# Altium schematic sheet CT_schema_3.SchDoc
size 283 x 147 mm
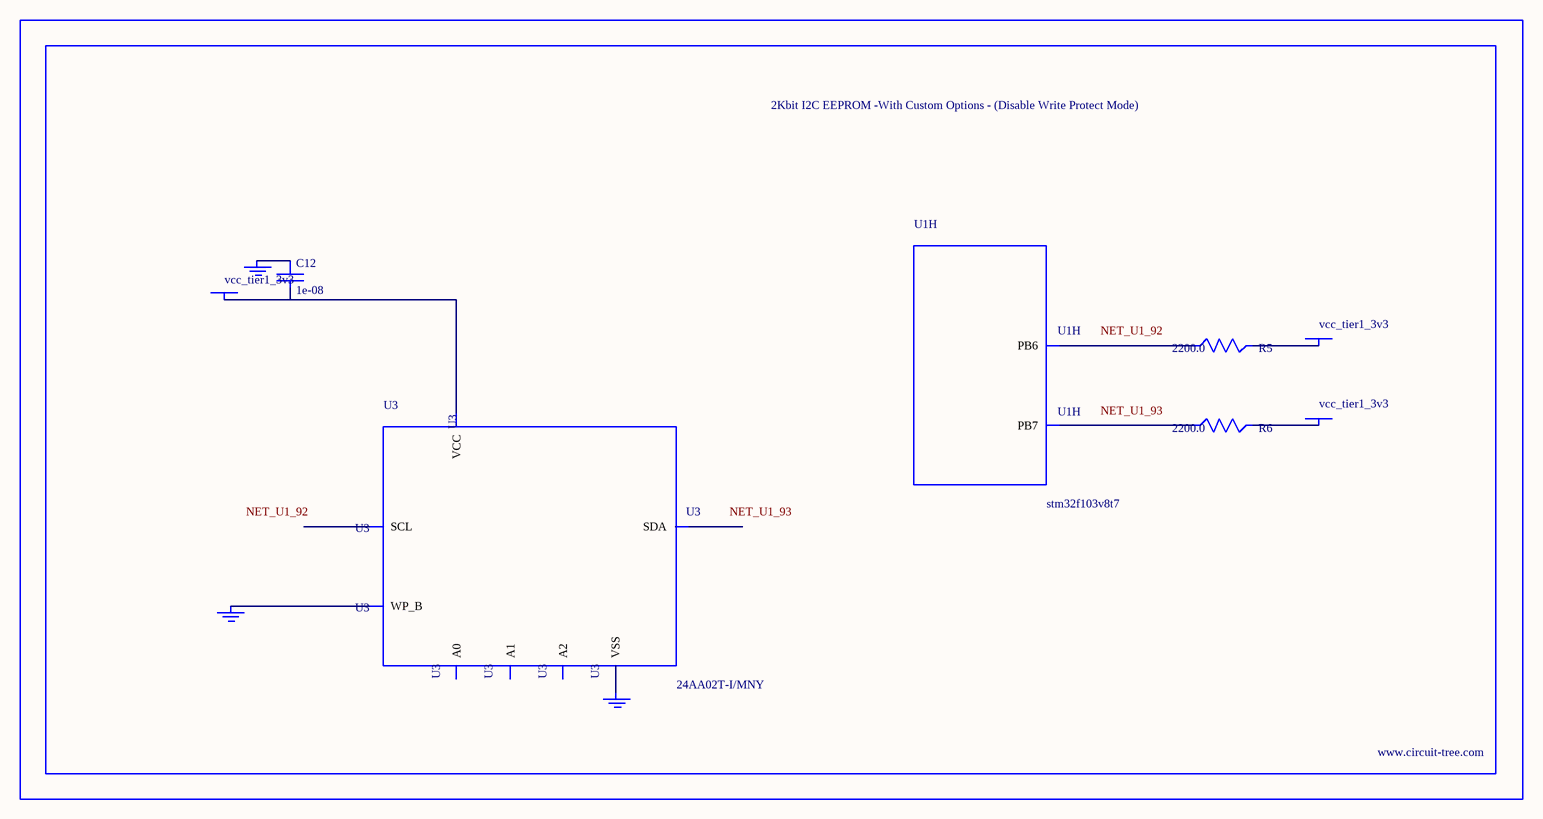
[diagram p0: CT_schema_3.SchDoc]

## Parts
BORDER2  (no value)
C12  1e-08  [C0402]
GND_INSTANCE_2_0  (no value)
GND_INSTANCE_2_1  (no value)
GND_INSTANCE_2_2  (no value)
POWER_INSTANCE_2_0  vcc_tier1_3v3
POWER_INSTANCE_2_1  vcc_tier1_3v3
POWER_INSTANCE_2_2  vcc_tier1_3v3
R5  2200.0  [R0603]
R6  2200.0  [R0603]
U1  stm32f103v8t7  [LQFP100]  (part H of 10)
U3  24AA02T-I/MNY  [TDFN-8/6MM]

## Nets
NetC12_1: C12.1 GND_INSTANCE_2_1.0(GND)
NetC12_2: C12.2 POWER_INSTANCE_2_0.0(PWR) U3.8(VCC)
NetGND_INSTANCE_2_0_0: GND_INSTANCE_2_0.0(GND) U3.7(WP_B)
NetGND_INSTANCE_2_2_0: GND_INSTANCE_2_2.0(GND) U3.4(VSS)
NetPOWER_INSTANCE_2_1_0: POWER_INSTANCE_2_1.0(PWR) R5.2
NetPOWER_INSTANCE_2_2_0: POWER_INSTANCE_2_2.0(PWR) R6.2
NetR5_1: R5.1 U1.92(PB6)
NetR6_1: R6.1 U1.93(PB7)

Not connected (* = marked no-connect by the designer): U3 1(A0) 2(A1) 3(A2) 5(SDA) 6(SCL)

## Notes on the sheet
- Labels drawn without touching a wire or pin: NET_U1_92, NET_U1_93

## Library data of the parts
BORDER2 = BORDER_PAGE2
C12 = C0402C103K3RAC
GND_INSTANCE_2_0-GND_INSTANCE_2_2 = GND
POWER_INSTANCE_2_0-POWER_INSTANCE_2_2 = PWR
R5 R6 = RC0603JR-072K2L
